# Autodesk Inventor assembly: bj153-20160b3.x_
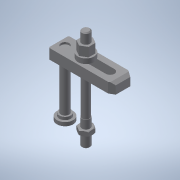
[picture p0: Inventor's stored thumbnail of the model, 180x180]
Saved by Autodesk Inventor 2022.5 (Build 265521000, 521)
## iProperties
Part Number: bj153-20160b3.x_
Material: 一般
Document SubType Name: Assembly
Designer: ImaoCorp
Sending System: SOLIDWORKS 2017-2017317
MC: AMD64
MC_MODEL: Intel64 Family 6 Model 60 Stepping 3, GenuineIntel
OS: Windows_NT
FRU: Parasolid Version 29.0, build 201,  4-17-2017
FORMAT: text
GUISE: transmit
KEY: bj153-20160b3
FILE: bj153-20160b3.x_t
DATE: Fri Mar 15 10:22:28 2019
Author: ImaoCorp
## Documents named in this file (6)
- X:\14_SW2022-Inv2022\00_全2023-1023新製品(TCC)まで\b\bj153-20160b3\BJ153-20160B3.iam
- X:\14_SW2022-Inv2022\00_全2023-1023新製品(TCC)まで\b\bj153-20160b3\bj153-20160b3_01.ipt
- X:\14_SW2022-Inv2022\00_全2023-1023新製品(TCC)まで\b\bj153-20160b3\bj153-20160b3_02.ipt
- X:\14_SW2022-Inv2022\00_全2023-1023新製品(TCC)まで\b\bj153-20160b3\bj153-20160b3_03.ipt
- X:\14_SW2022-Inv2022\00_全2023-1023新製品(TCC)まで\b\bj153-20160b3\bj153-20160b3_04.ipt
- X:\14_SW2022-Inv2022\00_全2023-1023新製品(TCC)まで\b\bj153-20160b3\bj153-20160b3_05.ipt
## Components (5 placed, 5 different names)
1. bj153-20160b3_01
2. bj153-20160b3_02
3. bj153-20160b3_03
4. bj153-20160b3_04
5. bj153-20160b3_05
